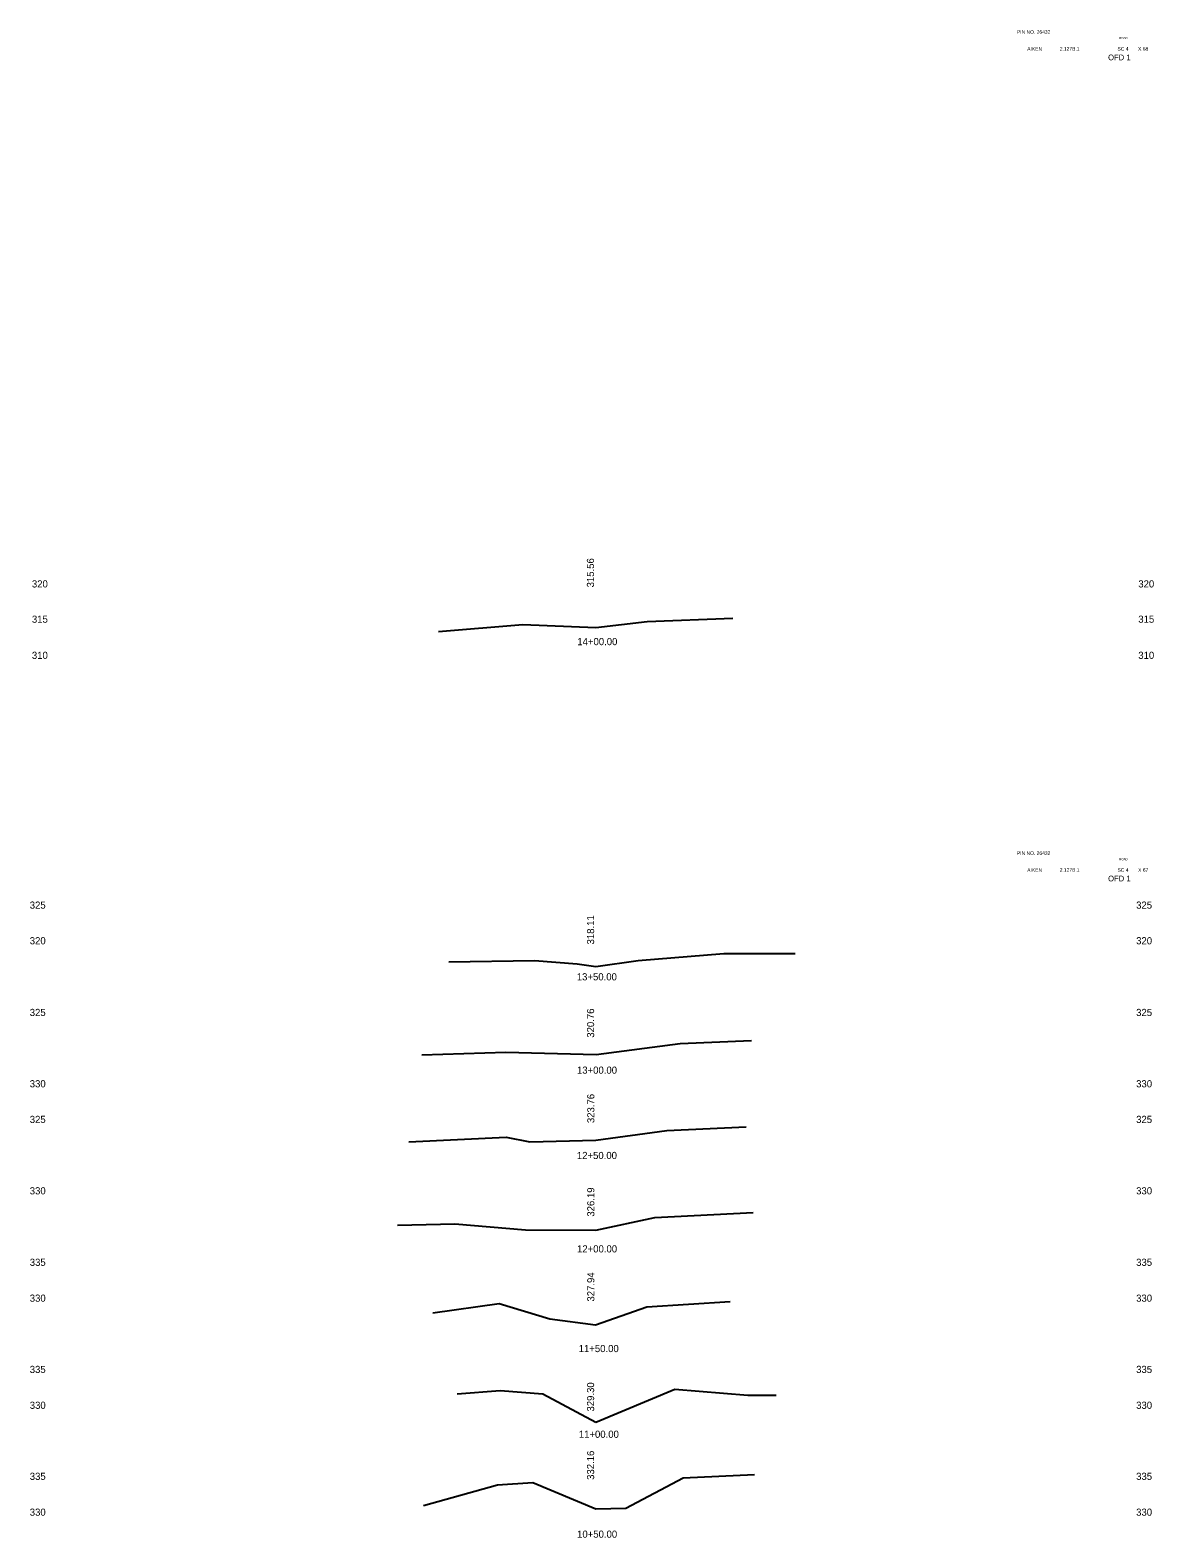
# Model space of a CAD drawing. Extents: x 1001 to 1158, y 1008 to 1219.
import ezdxf

# ---------------------------------------------------------------- set-up
doc = ezdxf.new("R2010")
doc.units = 0
for name, color, linetype in [('Level 1', 7, 'Continuous'), ('Level 10', 7, 'Continuous'), ('Level 3', 7, 'Continuous'), ('Level 60', 7, 'Continuous')]:
    doc.layers.add(name, color=color, linetype=linetype)

msp = doc.modelspace()

# ---------------------------------------------------------------- linework, layer by layer
at = {"layer": 'Level 60'}
for p, q in [((1057.98, 1135.02), (1069.81, 1135.99)), ((1057.98, 1135.02), (1069.81, 1135.99)), ((1069.81, 1135.99), (1080, 1135.56)), ((1069.81, 1135.99), (1080, 1135.56)), ((1080, 1135.56), (1087.19, 1136.39)), ((1080, 1135.56), (1087.19, 1136.39)), ((1087.19, 1136.39), (1099.19, 1136.89)), ((1087.19, 1136.39), (1099.19, 1136.89)), ((1085.95, 1088.92), (1097.94, 1089.92)), ((1097.94, 1089.92), (1107.94, 1089.92)), ((1059.41, 1088.75), (1071.41, 1088.95)), ((1071.41, 1088.95), (1077.41, 1088.45)), ((1077.41, 1088.45), (1080.02, 1088.11)), ((1080.02, 1088.11), (1085.95, 1088.92)), ((1080.04, 1075.75), (1091.84, 1077.32)), ((1091.84, 1077.32), (1101.84, 1077.72)), ((1055.62, 1075.72), (1067.43, 1076.11)), ((1067.43, 1076.11), (1080.04, 1075.75)), ((1053.83, 1063.55), (1067.47, 1064.18)), ((1067.47, 1064.18), (1070.75, 1063.56)), ((1080, 1063.76), (1089.98, 1065.14)), ((1089.98, 1065.14), (1101.06, 1065.62)), ((1070.75, 1063.56), (1080, 1063.76)), ((1088.27, 1052.93), (1102.08, 1053.65)), ((1052.25, 1051.86), (1060.24, 1052.06)), ((1060.24, 1052.06), (1070.15, 1051.23)), ((1080.02, 1051.19), (1088.27, 1052.93)), ((1070.15, 1051.23), (1080.02, 1051.19)), ((1057.16, 1039.58), (1066.48, 1040.89)), ((1066.48, 1040.89), (1073.57, 1038.73)), ((1087.17, 1040.44), (1098.84, 1041.19)), ((1079.99, 1037.93), (1087.17, 1040.44)), ((1073.57, 1038.73), (1079.99, 1037.93)), ((1060.6, 1028.23), (1066.6, 1028.73)), ((1066.6, 1028.73), (1072.6, 1028.23)), ((1072.6, 1028.23), (1080.02, 1024.29)), ((1080.02, 1024.29), (1091.08, 1028.91)), ((1091.08, 1028.91), (1101.3, 1028.06)), ((1101.3, 1028.06), (1105.3, 1028.06)), ((1066.25, 1015.49), (1071.2, 1015.82)), ((1071.2, 1015.82), (1080.01, 1012.16)), ((1084.2, 1012.23), (1092.24, 1016.47)), ((1092.24, 1016.47), (1102.24, 1016.97)), ((1055.89, 1012.6), (1066.25, 1015.49)), ((1080.01, 1012.16), (1084.2, 1012.23))]:
    msp.add_line(p, q, dxfattribs=at)

# ---------------------------------------------------------------- texts
at = {"layer": 'Level 1'}
for s, height, p in [('PIN NO. 26432', 0.5, (1139.01, 1218.71)), ('ROAD', 0.3, (1153.33, 1217.96)), ('AIKEN', 0.5, (1140.45, 1216.35)), (' 2.127B.1', 0.5, (1144.82, 1216.35)), ('SC 4', 0.5, (1153.1, 1216.35)), ('X 68', 0.5, (1155.98, 1216.35)), ('OFD 1', 0.8, (1151.78, 1215)), ('14+00.00', 1, (1077.42, 1133.09)), ('PIN NO. 26432', 0.5, (1139.01, 1103.72)), ('ROAD', 0.3, (1153.33, 1102.97)), ('AIKEN', 0.5, (1140.45, 1101.36)), (' 2.127B.1', 0.5, (1144.82, 1101.36)), ('OFD 1', 0.8, (1151.78, 1100.01)), ('SC 4', 0.5, (1153.1, 1101.36)), ('X 67', 0.5, (1155.99, 1101.36)), ('13+50.00', 1, (1077.35, 1086.15)), ('13+00.00', 1, (1077.37, 1073.08)), ('12+50.00', 1, (1077.36, 1061.13)), ('12+00.00', 1, (1077.38, 1048.05)), ('11+50.00', 1, (1077.61, 1034.09)), ('11+00.00', 1, (1077.63, 1022.09)), ('10+50.00', 1, (1077.39, 1008.1))]:
    msp.add_text(s, height=height, dxfattribs=at).set_placement(p)
at = {"layer": 'Level 10'}
for s, p in [('315.56', (1079.76, 1141.18)), ('318.11', (1079.78, 1091.18)), ('320.76', (1079.78, 1078.12)), ('323.76', (1079.81, 1066.16)), ('326.19', (1079.81, 1053.06)), ('327.94', (1079.81, 1041.17)), ('329.30', (1079.78, 1025.77)), ('332.16', (1079.78, 1016.2))]:
    msp.add_text(s, height=1, rotation=90, dxfattribs=at).set_placement(p)
at = {"layer": 'Level 3'}
for s, p in [(' 320', (1000.64, 1141.17)), (' 320', (1155.64, 1141.17)), (' 315', (1000.64, 1136.23)), (' 315', (1155.64, 1136.23)), (' 310', (1000.64, 1131.17)), (' 310', (1155.64, 1131.17)), (' 325', (1000.34, 1096.19)), (' 325', (1155.34, 1096.19)), (' 320', (1000.34, 1091.2)), (' 320', (1155.34, 1091.2)), (' 325', (1000.34, 1081.16)), (' 325', (1155.34, 1081.16)), (' 330', (1000.34, 1071.17)), (' 330', (1155.34, 1071.17)), (' 325', (1000.34, 1066.18)), (' 325', (1155.34, 1066.18)), (' 330', (1000.34, 1056.18)), (' 330', (1155.34, 1056.18)), (' 335', (1000.34, 1046.17)), (' 335', (1155.34, 1046.17)), (' 330', (1000.34, 1041.15)), (' 330', (1155.34, 1041.15)), (' 335', (1000.34, 1031.17)), (' 335', (1155.34, 1031.17)), (' 330', (1000.34, 1026.15)), (' 330', (1155.34, 1026.15)), (' 335', (1000.34, 1016.2)), (' 335', (1155.34, 1016.2)), (' 330', (1000.34, 1011.18)), (' 330', (1155.34, 1011.18))]:
    msp.add_text(s, height=1, dxfattribs=at).set_placement(p)

doc.saveas('drawing.dxf')
